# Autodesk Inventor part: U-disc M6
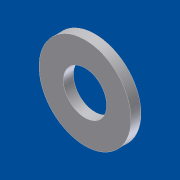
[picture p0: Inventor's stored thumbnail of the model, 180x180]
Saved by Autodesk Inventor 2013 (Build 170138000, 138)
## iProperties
Shininess: 69.0
Length Units: 11269
Angle Units: 11279
Time Units: 11290
Mass Units: 11283
Length Display Precision: 3
Angle Display Precision: 2
Created: 2001-04
Part Number: U-disc M6
Material: Standard
Document SubType Name: Modellieren
Designer: dl
Density: 1 g/cm^3
Density: 0.0
Volumn: 0.0
Area: 0.0
PropertySet Name: Model Information
Control State: 0
Master: False
Checked Out: False
Author: dl
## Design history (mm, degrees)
body "Solid1"
sketch "Sketch1"
  geometry: C1 r 6.9 at (-36.231, 18.491); C2 r 3.25 at (-36.231, 18.491)
  constraints: 2 centre point, 1 coincident
  dimensions: "d0" = 13.8 diameter of C1; "d1" = 6.5 diameter of C2
extrude "Extrusion1" new body sketch "Sketch1" distance "d2" = 1.5; taper "d3" = 0 deg
